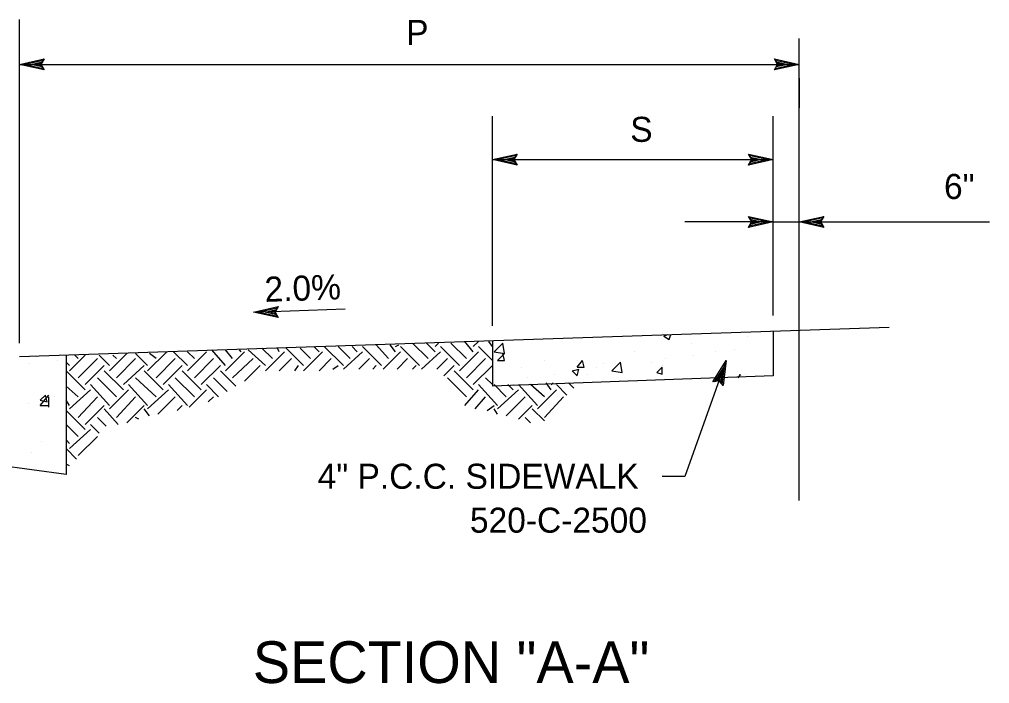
# Model space of a CAD drawing. Extents: x -118779 to -116979, y -104389 to -102939.
# Drawn here: x -118309 to -118076.7, y -103679 to -103519.8 of the extents above; entities that cross this region are included whole.
import ezdxf

# ---------------------------------------------------------------- set-up
doc = ezdxf.new("R2010")
doc.units = 0
for name, color, linetype in [('G-MARK', 7, 'Continuous'), ('G-TEXT', 7, 'Continuous'), ('Misc CnstDet(22)', 7, 'Continuous')]:
    doc.layers.add(name, color=color, linetype=linetype)

msp = doc.modelspace()

# ---------------------------------------------------------------- linework, layer by layer
at = {"layer": 'G-MARK'}
for p, q in [((-118309, -103597.39), (-118309, -103519.83)), ((-118309, -103530.62), (-118122.35, -103530.62)), ((-118195.77, -103593.25), (-118195.77, -103543.06)), ((-118128.58, -103590.76), (-118128.58, -103543.06)), ((-118195.77, -103553.43), (-118128.58, -103553.43)), ((-118128.58, -103568.36), (-118149.73, -103568.36)), ((-118128.58, -103568.36), (-118122.35, -103568.36)), ((-118122.35, -103568.36), (-118076.73, -103568.36)), ((-118252.92, -103589.97), (-118231.02, -103589.23))]:
    msp.add_line(p, q, dxfattribs=at)
msp.add_lwpolyline([(-118139.77, -103601.54), (-118149.73, -103629.33), (-118155.12, -103629.33)], dxfattribs=at)
at = {"layer": 'G-TEXT'}
for points in [[(-118303.09, -103531.94), (-118309, -103530.62), (-118303.09, -103529.31), (-118303.3, -103529.66), (-118307.63, -103530.61), (-118303.3, -103531.59), (-118303.51, -103531.24), (-118306.28, -103530.62), (-118303.51, -103530), (-118303.72, -103530.35), (-118304.92, -103530.62), (-118303.72, -103530.89), (-118303.88, -103530.62), (-118303.09, -103529.31), (-118303.88, -103530.62)], [(-118128.26, -103529.3), (-118122.35, -103530.62), (-118128.26, -103531.93), (-118128.05, -103531.58), (-118123.72, -103530.62), (-118128.05, -103529.65), (-118127.84, -103530), (-118125.07, -103530.61), (-118127.84, -103531.23), (-118127.63, -103530.88), (-118126.43, -103530.61), (-118127.63, -103530.34), (-118127.47, -103530.62), (-118128.26, -103531.93), (-118127.47, -103530.62)], [(-118189.86, -103554.75), (-118195.77, -103553.43), (-118189.86, -103552.12), (-118190.07, -103552.47), (-118194.4, -103553.42), (-118190.07, -103554.4), (-118190.28, -103554.05), (-118193.05, -103553.43), (-118190.28, -103552.82), (-118190.49, -103553.17), (-118191.69, -103553.43), (-118190.49, -103553.7), (-118190.65, -103553.43), (-118189.86, -103552.12), (-118190.65, -103553.43)], [(-118134.48, -103552.11), (-118128.58, -103553.43), (-118134.48, -103554.74), (-118134.27, -103554.39), (-118129.95, -103553.43), (-118134.27, -103552.46), (-118134.06, -103552.81), (-118131.3, -103553.43), (-118134.06, -103554.04), (-118133.85, -103553.69), (-118132.65, -103553.43), (-118133.86, -103553.16), (-118133.69, -103553.43), (-118134.48, -103554.74), (-118133.69, -103553.43)], [(-118134.48, -103567.04), (-118128.58, -103568.36), (-118134.48, -103569.67), (-118134.27, -103569.32), (-118129.95, -103568.36), (-118134.27, -103567.39), (-118134.06, -103567.74), (-118131.3, -103568.36), (-118134.06, -103568.97), (-118133.85, -103568.62), (-118132.65, -103568.36), (-118133.86, -103568.09), (-118133.69, -103568.36), (-118134.48, -103569.67), (-118133.69, -103568.36)], [(-118116.45, -103569.68), (-118122.35, -103568.36), (-118116.45, -103567.05), (-118116.66, -103567.4), (-118120.99, -103568.36), (-118116.66, -103569.33), (-118116.87, -103568.98), (-118119.64, -103568.36), (-118116.87, -103567.75), (-118117.08, -103568.1), (-118118.28, -103568.36), (-118117.07, -103568.63), (-118117.24, -103568.36), (-118116.45, -103567.05), (-118117.24, -103568.36)], [(-118247.02, -103591.29), (-118252.92, -103589.97), (-118247.01, -103588.66), (-118247.23, -103589.01), (-118251.55, -103589.97), (-118247.22, -103590.94), (-118247.43, -103590.59), (-118250.2, -103589.97), (-118247.44, -103589.36), (-118247.65, -103589.71), (-118248.84, -103589.97), (-118247.64, -103590.24), (-118247.8, -103589.97), (-118247.01, -103588.66), (-118247.8, -103589.97)], [(-118143, -103606.66), (-118139.77, -103601.54), (-118140.52, -103607.54), (-118140.78, -103607.23), (-118140.23, -103602.83), (-118142.6, -103606.58), (-118142.2, -103606.5), (-118140.69, -103604.1), (-118141.04, -103606.91), (-118141.3, -103606.6), (-118141.14, -103605.38), (-118141.8, -103606.42), (-118141.49, -103606.36), (-118140.52, -103607.54), (-118141.49, -103606.36)]]:
    msp.add_lwpolyline(points, close=True, dxfattribs=at)
at = {"layer": 'Misc CnstDet(22)'}
for p, q in [((-118122.35, -103635.14), (-118122.35, -103524.39)), ((-118122.35, -103530.2), (-118122.35, -103530.2)), ((-118122.35, -103530.62), (-118122.35, -103530.62)), ((-118122.35, -103533.93), (-118122.35, -103540.99)), ((-118128.58, -103553.43), (-118128.58, -103553.43)), ((-118128.58, -103590.76), (-118128.58, -103557.58)), ((-118122.35, -103566.7), (-118122.35, -103557.58)), ((-118122.35, -103568.36), (-118122.35, -103568.36)), ((-118122.35, -103570.43), (-118122.35, -103570.43)), ((-118100.79, -103593.66), (-118309, -103600.71)), ((-118154.71, -103595.73), (-118153.88, -103595.32)), ((-118154.71, -103595.73), (-118153.46, -103596.56)), ((-118153.46, -103596.56), (-118153.05, -103595.32)), ((-118134.8, -103595.73), (-118134.8, -103595.73)), ((-118128.58, -103594.49), (-118128.58, -103605.27)), ((-118128.58, -103594.49), (-118128.58, -103594.49)), ((-118128.58, -103594.49), (-118128.58, -103594.49)), ((-118237.24, -103599.47), (-118238.49, -103598.22)), ((-118231.44, -103602.79), (-118236, -103598.22)), ((-118229.78, -103601.13), (-118232.68, -103598.22)), ((-118228.12, -103599.47), (-118229.36, -103598.22)), ((-118228.12, -103598.22), (-118228.12, -103598.22)), ((-118222.31, -103602.79), (-118226.87, -103598.22)), ((-118220.65, -103601.13), (-118223.56, -103597.81)), ((-118218.99, -103599.47), (-118220.24, -103597.81)), ((-118218.99, -103598.22), (-118218.16, -103597.81)), ((-118213.19, -103602.79), (-118217.75, -103598.22)), ((-118211.11, -103601.13), (-118214.85, -103597.39)), ((-118209.45, -103599.47), (-118211.53, -103597.39)), ((-118209.45, -103598.22), (-118208.63, -103597.39)), ((-118203.65, -103602.79), (-118208.21, -103598.22)), ((-118201.99, -103601.13), (-118205.72, -103597.39)), ((-118200.33, -103599.47), (-118202.4, -103596.98)), ((-118200.33, -103598.22), (-118199.09, -103596.98)), ((-118195.77, -103601.54), (-118199.09, -103598.22)), ((-118195.77, -103598.22), (-118196.6, -103596.98)), ((-118195.77, -103596.98), (-118195.77, -103607.76)), ((-118195.77, -103596.98), (-118195.77, -103596.98)), ((-118195.35, -103599.47), (-118193.28, -103597.39)), ((-118192.86, -103599.88), (-118193.28, -103597.39)), ((-118148.07, -103597.39), (-118148.07, -103597.39)), ((-118297.8, -103600.3), (-118297.8, -103628.92)), ((-118296.97, -103604.03), (-118293.24, -103600.3)), ((-118294.9, -103601.13), (-118295.73, -103600.3)), ((-118287.43, -103602.79), (-118289.92, -103600.3)), ((-118287.43, -103604.03), (-118283.28, -103599.88)), ((-118285.77, -103601.13), (-118286.6, -103600.3)), ((-118278.31, -103602.79), (-118281.21, -103599.88)), ((-118278.31, -103604.03), (-118273.74, -103599.47)), ((-118276.23, -103601.13), (-118277.89, -103599.88)), ((-118268.77, -103602.79), (-118272.08, -103599.47)), ((-118267.11, -103601.13), (-118268.77, -103599.47)), ((-118268.77, -103604.03), (-118264.2, -103599.47)), ((-118259.64, -103602.79), (-118262.96, -103599.05)), ((-118257.98, -103601.13), (-118259.64, -103599.05)), ((-118259.64, -103604.03), (-118255.08, -103599.47)), ((-118255.91, -103599.47), (-118256.32, -103599.05)), ((-118250.1, -103602.79), (-118254.25, -103599.05)), ((-118248.44, -103601.13), (-118250.93, -103598.64)), ((-118250.1, -103604.03), (-118245.54, -103599.47)), ((-118246.78, -103599.47), (-118247.2, -103598.64)), ((-118240.98, -103602.79), (-118245.12, -103598.64)), ((-118239.32, -103601.13), (-118241.81, -103598.64)), ((-118240.98, -103604.03), (-118236.41, -103599.47)), ((-118231.44, -103603.61), (-118226.87, -103599.47)), ((-118221.9, -103603.61), (-118217.75, -103599.47)), ((-118212.77, -103603.61), (-118208.21, -103599.47)), ((-118203.65, -103604.03), (-118199.09, -103599.47)), ((-118195.35, -103599.47), (-118192.86, -103599.88)), ((-118194.52, -103601.54), (-118192.86, -103599.88)), ((-118192.86, -103601.54), (-118193.28, -103599.88)), ((-118161.76, -103599.47), (-118161.76, -103599.47)), ((-118147.66, -103600.3), (-118147.66, -103600.3)), ((-118142.26, -103599.47), (-118142.26, -103599.47)), ((-118137.7, -103599.05), (-118137.7, -103599.05)), ((-118309, -103600.71), (-118309, -103600.71)), ((-118306.51, -103602.37), (-118306.51, -103602.37)), ((-118304.85, -103600.71), (-118304.85, -103600.71)), ((-118299.87, -103601.54), (-118299.87, -103601.54)), ((-118296.97, -103602.79), (-118297.8, -103601.96)), ((-118294.9, -103605.69), (-118290.33, -103601.13)), ((-118293.24, -103607.35), (-118288.67, -103602.79)), ((-118285.77, -103605.69), (-118281.21, -103601.13)), ((-118284.11, -103607.35), (-118279.14, -103602.79)), ((-118276.23, -103605.69), (-118271.67, -103601.13)), ((-118274.57, -103607.35), (-118270.01, -103602.79)), ((-118267.11, -103605.69), (-118262.54, -103601.13)), ((-118265.45, -103607.35), (-118260.89, -103602.79)), ((-118257.98, -103605.69), (-118253.01, -103601.13)), ((-118255.08, -103606.52), (-118251.35, -103602.79)), ((-118246.78, -103604.03), (-118243.88, -103601.13)), ((-118243.05, -103604.03), (-118242.22, -103602.79)), ((-118237.24, -103604.03), (-118234.34, -103601.13)), ((-118233.93, -103603.61), (-118232.68, -103602.79)), ((-118227.7, -103603.61), (-118225.22, -103601.13)), ((-118224.39, -103603.61), (-118223.56, -103602.79)), ((-118218.58, -103603.61), (-118216.09, -103601.13)), ((-118214.85, -103603.61), (-118214.02, -103602.79)), ((-118209.04, -103603.61), (-118206.55, -103601.13)), ((-118207.38, -103605.27), (-118204.89, -103602.79)), ((-118201.99, -103605.69), (-118197.43, -103601.13)), ((-118200.33, -103607.35), (-118195.77, -103602.79)), ((-118194.52, -103601.54), (-118192.86, -103601.54)), ((-118183.32, -103601.54), (-118183.32, -103601.54)), ((-118175.44, -103601.54), (-118175.44, -103601.54)), ((-118175.44, -103603.2), (-118174.2, -103601.54)), ((-118173.79, -103603.2), (-118174.2, -103601.54)), ((-118169.22, -103602.37), (-118169.22, -103602.37)), ((-118167.15, -103604.03), (-118165.08, -103601.96)), ((-118164.66, -103604.44), (-118165.08, -103601.96)), ((-118157.61, -103601.96), (-118157.61, -103601.96)), ((-118155.12, -103602.79), (-118155.12, -103602.79)), ((-118154.29, -103601.13), (-118154.29, -103601.13)), ((-118293.24, -103608.59), (-118297.8, -103604.03)), ((-118284.11, -103608.59), (-118288.67, -103604.03)), ((-118274.57, -103608.59), (-118279.14, -103604.03)), ((-118265.45, -103608.59), (-118270.01, -103604.03)), ((-118257.15, -103607.76), (-118260.89, -103604.03)), ((-118251.35, -103604.03), (-118251.35, -103604.03)), ((-118200.33, -103608.59), (-118204.89, -103604.03)), ((-118128.58, -103605.27), (-118195.77, -103607.76)), ((-118188.72, -103603.2), (-118188.72, -103603.2)), ((-118180.84, -103604.86), (-118180.84, -103604.86)), ((-118176.69, -103604.03), (-118175.03, -103603.61)), ((-118176.69, -103604.03), (-118175.44, -103605.27)), ((-118175.44, -103603.2), (-118173.79, -103603.2)), ((-118175.44, -103605.27), (-118175.03, -103603.61)), ((-118172.96, -103604.86), (-118172.96, -103604.86)), ((-118170.88, -103603.2), (-118170.88, -103603.2)), ((-118167.15, -103604.03), (-118164.66, -103604.44)), ((-118156.37, -103604.44), (-118155.12, -103603.2)), ((-118156.37, -103604.44), (-118155.12, -103604.86)), ((-118155.12, -103604.86), (-118155.12, -103603.2)), ((-118141.02, -103603.61), (-118141.02, -103603.61)), ((-118136.87, -103605.69), (-118136.46, -103604.86)), ((-118136.46, -103605.27), (-118136.46, -103604.86)), ((-118136.04, -103605.27), (-118136.04, -103605.27)), ((-118135.21, -103604.86), (-118135.21, -103604.86)), ((-118287.43, -103612.32), (-118291.99, -103607.35)), ((-118285.77, -103610.25), (-118290.33, -103605.69)), ((-118278.31, -103612.32), (-118282.87, -103607.35)), ((-118276.23, -103610.25), (-118281.21, -103605.69)), ((-118268.77, -103612.32), (-118273.33, -103607.35)), ((-118267.11, -103610.25), (-118271.67, -103605.69)), ((-118261.3, -103610.25), (-118264.2, -103607.35)), ((-118259.23, -103609.01), (-118262.54, -103605.69)), ((-118201.99, -103610.25), (-118206.55, -103605.69)), ((-118194.52, -103612.32), (-118199.09, -103607.35)), ((-118195.77, -103607.35), (-118197.43, -103605.69)), ((-118192.45, -103610.25), (-118195.35, -103607.35)), ((-118190.79, -103608.59), (-118192.03, -103607.35)), ((-118190.79, -103607.35), (-118190.79, -103607.35)), ((-118184.98, -103612.32), (-118189.55, -103607.35)), ((-118187.47, -103605.69), (-118187.47, -103605.69)), ((-118183.32, -103610.25), (-118186.64, -103607.35)), ((-118181.67, -103608.59), (-118182.91, -103606.93)), ((-118181.67, -103607.35), (-118181.25, -103606.93)), ((-118177.93, -103609.84), (-118180.42, -103607.35)), ((-118176.27, -103608.18), (-118177.52, -103606.93)), ((-118304.02, -103612.32), (-118301.95, -103609.84)), ((-118304.02, -103611.08), (-118302.78, -103609.84)), ((-118302.36, -103611.5), (-118302.78, -103609.84)), ((-118294.9, -103610.25), (-118297.8, -103607.76)), ((-118296.97, -103613.15), (-118291.99, -103608.59)), ((-118287.43, -103613.15), (-118282.87, -103608.59)), ((-118278.31, -103613.15), (-118273.33, -103608.59)), ((-118268.35, -103612.74), (-118264.2, -103608.59)), ((-118202.4, -103612.32), (-118199.09, -103608.59)), ((-118194.52, -103613.15), (-118189.55, -103608.59)), ((-118184.98, -103613.15), (-118180.42, -103608.59)), ((-118306.92, -103611.91), (-118306.92, -103611.91)), ((-118304.02, -103611.08), (-118302.36, -103611.5)), ((-118301.95, -103612.74), (-118301.95, -103610.25)), ((-118300.7, -103610.25), (-118300.7, -103610.25)), ((-118296.97, -103612.32), (-118297.8, -103611.08)), ((-118294.9, -103615.23), (-118290.33, -103610.25)), ((-118285.77, -103615.23), (-118281.21, -103610.25)), ((-118275.82, -103614.4), (-118271.67, -103610.25)), ((-118263.79, -103611.5), (-118262.54, -103610.25)), ((-118199.92, -103613.15), (-118197.43, -103610.25)), ((-118192.45, -103614.81), (-118187.89, -103610.25)), ((-118183.32, -103615.23), (-118178.76, -103610.25)), ((-118304.02, -103612.32), (-118301.95, -103612.32)), ((-118293.24, -103618.13), (-118297.8, -103613.57)), ((-118293.24, -103616.89), (-118288.67, -103612.32)), ((-118285.36, -103616.89), (-118288.67, -103613.15)), ((-118283.28, -103616.47), (-118279.14, -103612.32)), ((-118277.89, -103614.81), (-118279.14, -103613.15)), ((-118271.25, -103613.57), (-118270.01, -103612.32)), ((-118197.01, -103613.57), (-118195.35, -103612.32)), ((-118194.52, -103614.4), (-118195.35, -103613.15)), ((-118189.55, -103615.64), (-118186.23, -103612.32)), ((-118183.32, -103616.06), (-118186.23, -103613.15)), ((-118294.9, -103619.79), (-118297.8, -103616.89)), ((-118289.92, -103618.96), (-118291.99, -103616.89)), ((-118288.26, -103617.3), (-118290.33, -103615.23)), ((-118280.38, -103615.64), (-118281.21, -103615.23)), ((-118186.64, -103616.47), (-118187.89, -103615.23)), ((-118296.97, -103622.69), (-118291.99, -103618.13)), ((-118297.8, -103628.92), (-118352.96, -103621.45)), ((-118303.61, -103621.03), (-118303.61, -103621.03)), ((-118296.97, -103621.45), (-118297.8, -103620.62)), ((-118294.9, -103624.35), (-118290.33, -103619.79)), ((-118306.09, -103623.52), (-118306.09, -103623.52)), ((-118295.31, -103625.18), (-118297.8, -103622.69)), ((-118296.97, -103626.84), (-118297.8, -103626.43))]:
    msp.add_line(p, q, dxfattribs=at)

# ---------------------------------------------------------------- texts
for s, height, p in [('P', 6, (-118216.41, -103525.96)), ('S', 6, (-118162.76, -103549.18)), ('6"', 6, (-118087.64, -103562.87)), ('4" P.C.C. SIDEWALK', 6, (-118237.59, -103632.31)), ('520-C-2500', 6, (-118201.14, -103642.84)), ('SECTION "A-A"', 10, (-118253.12, -103678.86))]:
    msp.add_text(s, height=height, dxfattribs=at).set_placement(p)
msp.add_text('2.0%', height=6, rotation=2.0152, dxfattribs=at).set_placement((-118250.21, -103587.54))

doc.saveas('drawing.dxf')
